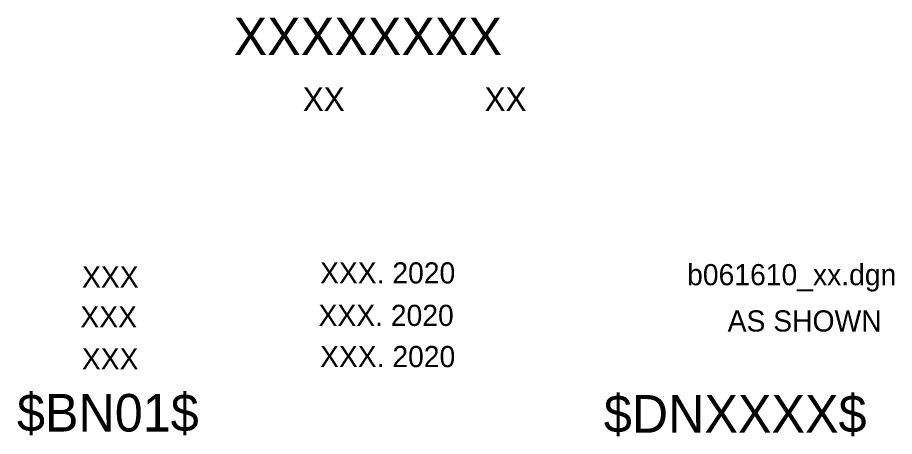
# Model space of a CAD drawing. Extents: x 2.34 to 2.78, y 0.06 to 1.72.
import ezdxf

# ---------------------------------------------------------------- set-up
doc = ezdxf.new("R2010")
doc.units = 0
doc.layers.add('B-Tbl-Prelim', color=7, linetype='Continuous')
doc.layers.add('B-Tbl-Title Block', color=7, linetype='Continuous')

msp = doc.modelspace()

# ---------------------------------------------------------------- texts
at = {"layer": 'B-Tbl-Prelim'}
for s, height, p in [('XXXXXXXX', 0.016667, (2.43492, 0.22527)), ('XX', 0.010417, (2.46555, 0.20052)), ('XX', 0.010417, (2.54612, 0.20052)), ('$BN01$', 0.016667, (2.33886, 0.05846)), ('$DNXXXX$', 0.016667, (2.59899, 0.05797))]:
    msp.add_text(s, height=height, rotation=0, dxfattribs=at).set_placement(p)
at = {"layer": 'B-Tbl-Title Block'}
for s, p in [('XXX. 2020', (2.47319, 0.12409)), ('b061610_xx.dgn', (2.63591, 0.1233)), ('XXX', (2.36767, 0.12229)), ('XXX', (2.36696, 0.10465)), ('XXX. 2020', (2.47252, 0.10526)), ('AS SHOWN', (2.65388, 0.10279)), ('XXX', (2.36761, 0.08601)), ('XXX. 2020', (2.47319, 0.08701))]:
    msp.add_text(s, height=0.009375, rotation=0, dxfattribs=at).set_placement(p)

doc.saveas('drawing.dxf')
